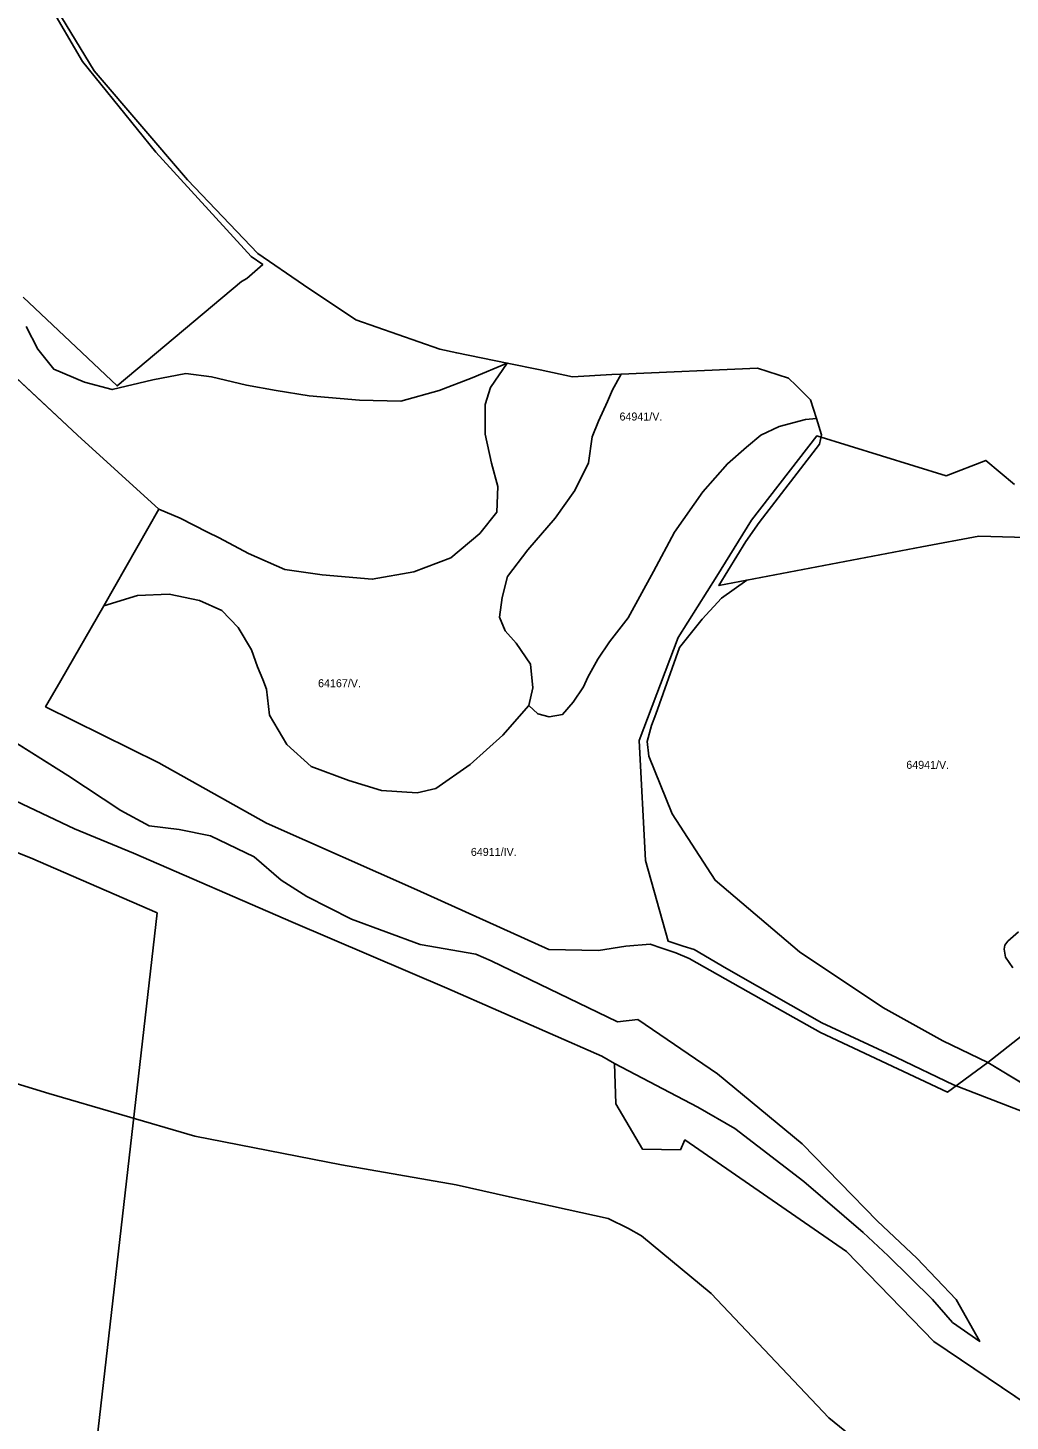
# Model space of a CAD drawing. Extents: x -521621 to -516761, y -1190184 to -1184927.
# Drawn here: x -520304 to -519813, y -1187109 to -1186412 of the extents above; entities that cross this region are included whole.
import ezdxf

# ---------------------------------------------------------------- set-up
doc = ezdxf.new("R2010")
doc.units = 0
doc.layers.add('BPEJ_s', color=7, linetype='Continuous')
doc.layers.add('odvodneni_s', color=7, linetype='Continuous')

msp = doc.modelspace()

# ---------------------------------------------------------------- linework, layer by layer
at = {"layer": 'BPEJ_s'}
for p, q in [((-520323.03, -1186575), (-520279.03, -1186615.98)), ((-520279.03, -1186615.98), (-520238.35, -1186653.08)), ((-520238.35, -1186653.08), (-520265.96, -1186701.27)), ((-520265.96, -1186701.27), (-520287.36, -1186738.62)), ((-520287.36, -1186738.62), (-520294.98, -1186751.77)), ((-520294.98, -1186751.77), (-520238.41, -1186779.86)), ((-520283.95, -1186786.12), (-520320.58, -1186763.12)), ((-520238.41, -1186779.86), (-520184.56, -1186809.97)), ((-520257.46, -1186803.64), (-520283.95, -1186786.12)), ((-520243.18, -1186811.29), (-520257.46, -1186803.64)), ((-520184.56, -1186809.97), (-520109.39, -1186843.32)), ((-520228.27, -1186813.21), (-520243.18, -1186811.29)), ((-520212.63, -1186816.31), (-520228.27, -1186813.21)), ((-520190.78, -1186826.8), (-520212.63, -1186816.31)), ((-520177.21, -1186838.47), (-520190.78, -1186826.8)), ((-520164.47, -1186846.59), (-520177.21, -1186838.47)), ((-520109.39, -1186843.32), (-520043.44, -1186873.16)), ((-520142.08, -1186857.96), (-520164.47, -1186846.59)), ((-520107.67, -1186870.67), (-520142.08, -1186857.96)), ((-520079.93, -1186875.52), (-520107.67, -1186870.67)), ((-520018.6, -1186873.61), (-520004.97, -1186871.41)), ((-520004.97, -1186871.41), (-519992.67, -1186870.56)), ((-519992.67, -1186870.56), (-519986.85, -1186872.5)), ((-519986.85, -1186872.5), (-519979.94, -1186874.8)), ((-520072.25, -1186878.86), (-520079.93, -1186875.52)), ((-520009.1, -1186909.3), (-520072.25, -1186878.86)), ((-520043.44, -1186873.16), (-520018.6, -1186873.61)), ((-519979.94, -1186874.8), (-519973.29, -1186877.63)), ((-519973.29, -1186877.63), (-519933.36, -1186900.2)), ((-519933.36, -1186900.2), (-519907.59, -1186914.66)), ((-519998.86, -1186908.09), (-520009.1, -1186909.3)), ((-519959.08, -1186935.39), (-519998.86, -1186908.09)), ((-519907.59, -1186914.66), (-519843.99, -1186944.45)), ((-520009.92, -1186950.25), (-520010.6, -1186930.08)), ((-520010.6, -1186930.08), (-519968.93, -1186952.07)), ((-519916.65, -1186970.27), (-519959.08, -1186935.39)), ((-519843.99, -1186944.45), (-519823.86, -1186929.63)), ((-519823.86, -1186929.63), (-519762.29, -1186966.96)), ((-519996.59, -1186972.93), (-520009.92, -1186950.25)), ((-519968.93, -1186952.07), (-519950.37, -1186962.69)), ((-519950.37, -1186962.69), (-519915.89, -1186989.23)), ((-519975.37, -1186968.38), (-519977.64, -1186973.31)), ((-519894.52, -1187024.1), (-519975.37, -1186968.38)), ((-519977.64, -1186973.31), (-519996.59, -1186972.93)), ((-519879.14, -1187008.95), (-519916.65, -1186970.27)), ((-519915.89, -1186989.23), (-519886.22, -1187014.63)), ((-519859.39, -1187027.54), (-519879.14, -1187008.95)), ((-519886.22, -1187014.63), (-519873.73, -1187026.37)), ((-519850.94, -1187069.23), (-519894.52, -1187024.1)), ((-519873.73, -1187026.37), (-519851.54, -1187048.17)), ((-519839.76, -1187048.17), (-519859.39, -1187027.54)), ((-519851.54, -1187048.17), (-519841.52, -1187059.63)), ((-519827.98, -1187069.12), (-519839.76, -1187048.17)), ((-519841.52, -1187059.63), (-519827.98, -1187069.12)), ((-519796.11, -1187106.16), (-519850.94, -1187069.23))]:
    msp.add_line(p, q, dxfattribs=at)
for points in [[(-520287.12, -1186407.06), (-520270.66, -1186433.76), (-520224.12, -1186488.31), (-520188.81, -1186525.19), (-520166.06, -1186540.77), (-520139.85, -1186558.3), (-520097.96, -1186573.08), (-520089.46, -1186574.89), (-520064.18, -1186579.99), (-520081.67, -1186587.33), (-520098.18, -1186593.72), (-520117.35, -1186599.05), (-520138.11, -1186598.52), (-520163.14, -1186596.38), (-520179.64, -1186593.72), (-520194.55, -1186591.06), (-520212.12, -1186586.79), (-520224.9, -1186585.2), (-520241.4, -1186588.39), (-520261.64, -1186593.19), (-520275.48, -1186589.46), (-520290.92, -1186583.06), (-520298.91, -1186572.94), (-520304.77, -1186561.75)], [(-519751.33, -1186668.69), (-519828.47, -1186666.52), (-519856.86, -1186671.78), (-519944.34, -1186688.5), (-519958.34, -1186691.17), (-519944.91, -1186669.14), (-519938.31, -1186659.66), (-519908.09, -1186620.42), (-519907.04, -1186615.79), (-519909.62, -1186607.64), (-519912.56, -1186598.31), (-519919.72, -1186591.14), (-519923.6, -1186587.56), (-519939.12, -1186582.48), (-520007.29, -1186585.48), (-520011.92, -1186585.69), (-520031.5, -1186586.84), (-520047.8, -1186583.29), (-520064.18, -1186579.99), (-520089.46, -1186574.89), (-520097.96, -1186573.08), (-520139.85, -1186558.3), (-520166.06, -1186540.77), (-520188.81, -1186525.19), (-520224.12, -1186488.31), (-520270.66, -1186433.76), (-520287.12, -1186407.06)], [(-520304.77, -1186561.75), (-520298.91, -1186572.94), (-520290.92, -1186583.06), (-520275.48, -1186589.46), (-520261.64, -1186593.19), (-520241.4, -1186588.39), (-520224.9, -1186585.2), (-520212.12, -1186586.79), (-520194.55, -1186591.06), (-520179.64, -1186593.72), (-520163.14, -1186596.38), (-520138.11, -1186598.52), (-520117.35, -1186599.05), (-520098.18, -1186593.72), (-520081.67, -1186587.33), (-520064.18, -1186579.99), (-520072.62, -1186592.12), (-520075.28, -1186600.65), (-520075.28, -1186615.56), (-520072.09, -1186629.95), (-520068.89, -1186641.67), (-520069.43, -1186654.46), (-520077.94, -1186665.11), (-520092.32, -1186677.37), (-520110.96, -1186684.29), (-520131.72, -1186688.02), (-520156.75, -1186685.89), (-520175.38, -1186683.23), (-520193.48, -1186675.24), (-520208.21, -1186667.35), (-520214.12, -1186664.53), (-520227.66, -1186657.48), (-520238.35, -1186653.08), (-520279.03, -1186615.98), (-520323.03, -1186575)], [(-519806.72, -1186916.18), (-519823.86, -1186929.63), (-519846.43, -1186918.76), (-519876.36, -1186902.18), (-519918.06, -1186874.36), (-519960.29, -1186838.52), (-519981.67, -1186805.36), (-519993.43, -1186776.48), (-519994.19, -1186769.16), (-519992.03, -1186761.13), (-519989.93, -1186755.47), (-519978.05, -1186722.09), (-519966.7, -1186707.96), (-519957.12, -1186697.45), (-519944.34, -1186688.5), (-519856.86, -1186671.78), (-519828.47, -1186666.52), (-519751.33, -1186668.69)], [(-520320.58, -1186763.12), (-520283.95, -1186786.12), (-520257.46, -1186803.64), (-520243.18, -1186811.29), (-520228.27, -1186813.21), (-520212.63, -1186816.31), (-520190.78, -1186826.8), (-520177.21, -1186838.47), (-520164.47, -1186846.59), (-520142.08, -1186857.96), (-520107.67, -1186870.67), (-520079.93, -1186875.52), (-520072.25, -1186878.86), (-520009.1, -1186909.3), (-519998.86, -1186908.09), (-519959.08, -1186935.39), (-519916.65, -1186970.27), (-519879.14, -1187008.95), (-519859.39, -1187027.54), (-519839.76, -1187048.17), (-519827.98, -1187069.12), (-519841.52, -1187059.63), (-519851.54, -1187048.17), (-519873.73, -1187026.37), (-519886.22, -1187014.63), (-519915.89, -1186989.23), (-519950.37, -1186962.69), (-519968.93, -1186952.07), (-520010.6, -1186930.08), (-520016.95, -1186926.52), (-520094.47, -1186892.41), (-520171.15, -1186859.64), (-520250.97, -1186824.96), (-520280.59, -1186812.77), (-520313.26, -1186797.34)], [(-520313.26, -1186797.34), (-520280.59, -1186812.77), (-520250.97, -1186824.96), (-520171.15, -1186859.64), (-520094.47, -1186892.41), (-520016.95, -1186926.52), (-520010.6, -1186930.08)], [(-519811.48, -1186882.36), (-519815.13, -1186876.93), (-519815.8, -1186873), (-519815.35, -1186870.97), (-519813.86, -1186869.02), (-519808.63, -1186864.26)], [(-519808.63, -1186864.26), (-519813.86, -1186869.02), (-519815.35, -1186870.97), (-519815.8, -1186873), (-519815.13, -1186876.93), (-519811.48, -1186882.36)], [(-519762.29, -1186966.96), (-519823.86, -1186929.63), (-519806.72, -1186916.18)], [(-520336.48, -1186932.05), (-520293.42, -1186945.16), (-520220.4, -1186966.52), (-520147.01, -1186980.75), (-520089.73, -1186990.87), (-520063.14, -1186996.86), (-520013.72, -1187007.73), (-520003.61, -1187012.6), (-519997.04, -1187016.38), (-519962.17, -1187045.11), (-519903.36, -1187107.38), (-519856.17, -1187145.7)], [(-519856.17, -1187145.7), (-519903.36, -1187107.38), (-519962.17, -1187045.11), (-519997.04, -1187016.38), (-520003.61, -1187012.6), (-520013.72, -1187007.73), (-520063.14, -1186996.86), (-520089.73, -1186990.87), (-520147.01, -1186980.75), (-520220.4, -1186966.52), (-520293.42, -1186945.16), (-520336.48, -1186932.05)], [(-520010.6, -1186930.08), (-520009.92, -1186950.25), (-519996.59, -1186972.93), (-519977.64, -1186973.31), (-519975.37, -1186968.38), (-519894.52, -1187024.1), (-519850.94, -1187069.23), (-519796.11, -1187106.16)]]:
    msp.add_lwpolyline(points, dxfattribs=at)
for points in [[(-520265.96, -1186701.27), (-520238.35, -1186653.08), (-520227.66, -1186657.48), (-520214.12, -1186664.53), (-520208.21, -1186667.35), (-520193.48, -1186675.24), (-520175.38, -1186683.23), (-520156.75, -1186685.89), (-520131.72, -1186688.02), (-520110.96, -1186684.29), (-520092.32, -1186677.37), (-520077.94, -1186665.11), (-520069.43, -1186654.46), (-520068.89, -1186641.67), (-520072.09, -1186629.95), (-520075.28, -1186615.56), (-520075.28, -1186600.65), (-520072.62, -1186592.12), (-520064.18, -1186579.99), (-520047.8, -1186583.29), (-520031.5, -1186586.84), (-520011.92, -1186585.69), (-520007.29, -1186585.48), (-520011.5, -1186593.35), (-520014.14, -1186599.1), (-520018.57, -1186609.06), (-520021.69, -1186616.77), (-520023.54, -1186629.75), (-520030.34, -1186643.66), (-520040.22, -1186657.57), (-520053.82, -1186673.34), (-520064.01, -1186686.63), (-520066.79, -1186697.14), (-520068.03, -1186707.03), (-520065.25, -1186713.83), (-520059.68, -1186720.01), (-520052.58, -1186730.52), (-520051.34, -1186742.27), (-520053.45, -1186751.12), (-520066.41, -1186766.07), (-520082.76, -1186780.74), (-520099.96, -1186792.58), (-520109.26, -1186794.84), (-520127.02, -1186793.71), (-520143.37, -1186788.63), (-520162.26, -1186781.58), (-520174.38, -1186770.58), (-520183.12, -1186755.92), (-520184.53, -1186742.94), (-520186.34, -1186738.08), (-520189.11, -1186731.76), (-520192.07, -1186723.26), (-520198.78, -1186712.2), (-520206.88, -1186703.7), (-520218.07, -1186698.66), (-520233.29, -1186695.55), (-520249.08, -1186696.12)], [(-520053.45, -1186751.12), (-520051.34, -1186742.27), (-520052.58, -1186730.52), (-520059.68, -1186720.01), (-520065.25, -1186713.83), (-520068.03, -1186707.03), (-520066.79, -1186697.14), (-520064.01, -1186686.63), (-520053.82, -1186673.34), (-520040.22, -1186657.57), (-520030.34, -1186643.66), (-520023.54, -1186629.75), (-520021.69, -1186616.77), (-520018.57, -1186609.06), (-520014.14, -1186599.1), (-520011.5, -1186593.35), (-520007.29, -1186585.48), (-519939.12, -1186582.48), (-519923.6, -1186587.56), (-519919.72, -1186591.14), (-519912.56, -1186598.31), (-519909.62, -1186607.64), (-519915.03, -1186608.23), (-519928.16, -1186611.63), (-519937.43, -1186616.04), (-519944.53, -1186622.06), (-519954.11, -1186630.26), (-519966.39, -1186644.37), (-519980.57, -1186664.51), (-519991.13, -1186684.12), (-520003.74, -1186707.33), (-520013.04, -1186719.4), (-520018.91, -1186728.05), (-520023.85, -1186737.02), (-520026.1, -1186741.81), (-520031.18, -1186749.43), (-520036.53, -1186755.63), (-520043.3, -1186756.76), (-520048.93, -1186755.35)], [(-520265.96, -1186701.27), (-520249.08, -1186696.12), (-520233.29, -1186695.55), (-520218.07, -1186698.66), (-520206.88, -1186703.7), (-520198.78, -1186712.2), (-520192.07, -1186723.26), (-520189.11, -1186731.76), (-520186.34, -1186738.08), (-520184.53, -1186742.94), (-520183.12, -1186755.92), (-520174.38, -1186770.58), (-520162.26, -1186781.58), (-520143.37, -1186788.63), (-520127.02, -1186793.71), (-520109.26, -1186794.84), (-520099.96, -1186792.58), (-520082.76, -1186780.74), (-520066.41, -1186766.07), (-520053.45, -1186751.12), (-520048.93, -1186755.35), (-520043.3, -1186756.76), (-520036.53, -1186755.63), (-520031.18, -1186749.43), (-520026.1, -1186741.81), (-520023.85, -1186737.02), (-520018.91, -1186728.05), (-520013.04, -1186719.4), (-520003.74, -1186707.33), (-519991.13, -1186684.12), (-519980.57, -1186664.51), (-519966.39, -1186644.37), (-519954.11, -1186630.26), (-519944.53, -1186622.06), (-519937.43, -1186616.04), (-519928.16, -1186611.63), (-519915.03, -1186608.23), (-519909.62, -1186607.64), (-519907.04, -1186615.79), (-519908.09, -1186620.42), (-519938.31, -1186659.66), (-519944.91, -1186669.14), (-519958.34, -1186691.17), (-519944.34, -1186688.5), (-519957.12, -1186697.45), (-519966.7, -1186707.96), (-519978.05, -1186722.09), (-519989.93, -1186755.47), (-519992.03, -1186761.13), (-519994.19, -1186769.16), (-519993.43, -1186776.48), (-519981.67, -1186805.36), (-519960.29, -1186838.52), (-519918.06, -1186874.36), (-519876.36, -1186902.18), (-519846.43, -1186918.76), (-519823.86, -1186929.63), (-519843.99, -1186944.45), (-519907.59, -1186914.66), (-519933.36, -1186900.2), (-519973.29, -1186877.63), (-519979.94, -1186874.8), (-519986.85, -1186872.5), (-519992.67, -1186870.56), (-520004.97, -1186871.41), (-520018.6, -1186873.61), (-520043.44, -1186873.16), (-520109.39, -1186843.32), (-520184.56, -1186809.97), (-520238.41, -1186779.86), (-520294.98, -1186751.77), (-520287.36, -1186738.62)]]:
    msp.add_lwpolyline(points, close=True, dxfattribs=at)
at = {"layer": 'odvodneni_s'}
for points in [[(-520293.78, -1186399.85), (-520276.48, -1186429.13), (-520239.88, -1186474.43), (-520192.2, -1186526.59), (-520186.41, -1186530.62), (-520194.38, -1186537.66), (-520197.01, -1186539.14), (-520259.28, -1186591.36), (-520306.17, -1186546.93)], [(-519763.11, -1186970.98), (-519841.01, -1186940.74), (-519869.52, -1186927.22), (-519906.88, -1186909.9), (-519954.56, -1186882.72), (-519970.65, -1186873.19), (-519976.16, -1186871.44), (-519983.71, -1186869.01), (-519994.98, -1186828.71), (-519998.27, -1186768.66), (-519978.77, -1186717.2), (-519959.37, -1186686.46), (-519942.01, -1186658.58), (-519909.43, -1186616.41), (-519844.71, -1186636.32), (-519824.93, -1186628.66), (-519810.64, -1186640.61)], [(-520280.02, -1187212.1), (-520239.28, -1186854.88), (-520302.62, -1186827.36), (-520387.86, -1186793.32)]]:
    msp.add_lwpolyline(points, dxfattribs=at)

# ---------------------------------------------------------------- texts
at = {"layer": 'BPEJ_s'}
for s, p in [('64941/V.', (-520008.05, -1186608.67)), ('64167/V.', (-520158.77, -1186742.03)), ('64941/V.', (-519864.67, -1186782.83)), ('64911/IV.', (-520082.37, -1186826.37))]:
    msp.add_text(s, height=4, dxfattribs=at).set_placement(p)

doc.saveas('drawing.dxf')
